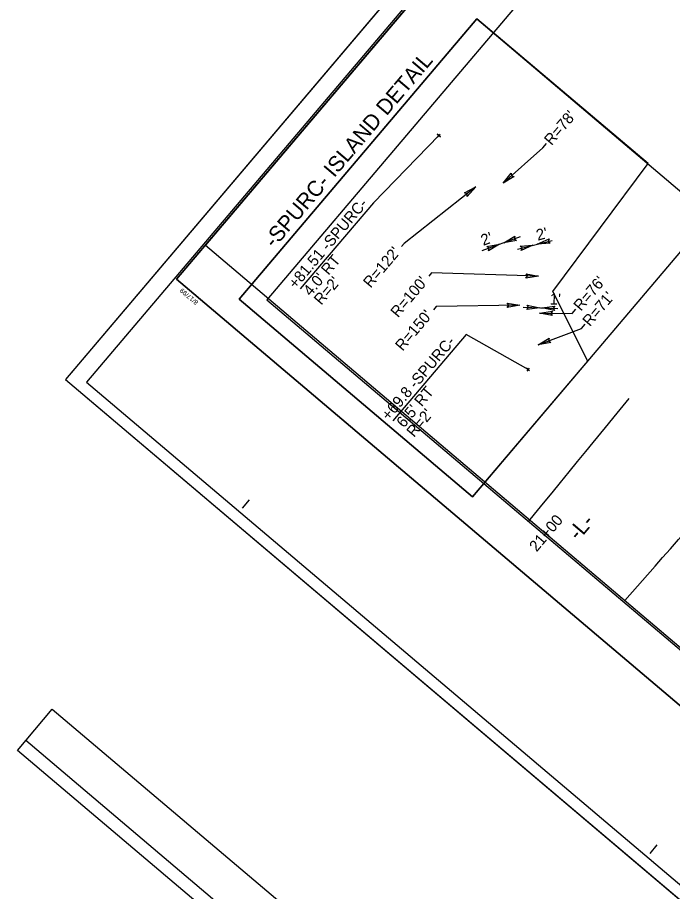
# Model space of a CAD drawing. Extents: x 1761753 to 1762923, y 422186 to 423380.
# Drawn here: x 1761753.2 to 1762047.4, y 422600.2 to 422992.9 of the extents above; entities that cross this region are included whole.
import ezdxf

# ---------------------------------------------------------------- set-up
doc = ezdxf.new("R2010")
doc.units = 0
for name, color, linetype in [('Default', 7, 'Continuous'), ('Prop Conc 2ft 6in Curb and Gutter', 7, 'Continuous'), ('Prop Conc 5in Monolithic Keyed In Island', 7, 'Continuous'), ('Prop Dimension Text', 7, 'Continuous'), ('Prop Grid Mask', 7, 'Continuous'), ('Prop Horizontal Alignment Station Label', 7, 'Continuous'), ('Prop RDY Traffic Signal CELL', 7, 'Continuous'), ('Prop Shade Heavy', 7, 'Continuous'), ('Sheet Cutting Line CELL', 7, 'Continuous'), ('Sheet Data Field CELL', 7, 'Continuous'), ('Sheet North Arrow CELL', 7, 'Continuous'), ('Sheet Plan CELL', 7, 'Continuous'), ('Sheet Plot Border Outside CELL', 7, 'Continuous'), ('Sheet Symbology CELL', 7, 'Continuous')]:
    doc.layers.add(name, color=color, linetype=linetype)

# ---------------------------------------------------------------- blocks, each defined once
blk = doc.blocks.new('Terminator')
at = {"layer": 'Sheet Data Field CELL'}
blk.add_lwpolyline([(-9, 1.55), (0, 0), (-9.05, -1.6), (-7.9, 0)], close=True, dxfattribs=at)

msp = doc.modelspace()

# ---------------------------------------------------------------- linework, layer by layer
at = {"layer": 'Default'}
for p, q in [((1761942.31, 422939.98), (1761941.73, 422940.47)), ((1761943.14, 422939.28), (1761942.31, 422939.98)), ((1761982.36, 422834.9), (1761981.78, 422835.39)), ((1761983.19, 422834.2), (1761982.36, 422834.9))]:
    msp.add_line(p, q, dxfattribs=at)
at = {"layer": 'Prop Conc 2ft 6in Curb and Gutter'}
msp.add_lwpolyline([(1762106.21, 422556.31), (1762536.95, 423064.78), (1762214.97, 423337.56), (1761784.22, 422829.09)], close=True, dxfattribs=at)
at = {"layer": 'Prop Conc 5in Monolithic Keyed In Island'}
msp.add_lwpolyline([(1761852.77, 422866.3), (1761959.54, 422992.34), (1762064.33, 422903.57), (1761957.56, 422777.53)], close=True, dxfattribs=at)
at = {"layer": 'Prop Dimension Text'}
for p, q in [((1762210.03, 423344.1), (1761774.75, 422830.29)), ((1761774.75, 422830.29), (1762108.95, 422547.17))]:
    msp.add_line(p, q, dxfattribs=at)
at = {"layer": 'Prop Grid Mask'}
for p, q in [((1761824.66, 422875.29), (1761824.66, 422875.29)), ((1761854.18, 422772.43), (1761857.41, 422776.26)), ((1762037.31, 422617.31), (1762040.54, 422621.12))]:
    msp.add_line(p, q, dxfattribs=at)
for points in [[(1762212.5, 423333.11), (1761824.66, 422875.29), (1762145.13, 422603.81), (1762532.96, 423061.62)], [(1762145.13, 422603.81), (1761824.66, 422875.28), (1762160.77, 423272.05), (1762206.57, 423233.25), (1762258.3, 423294.3), (1762532.96, 423061.62)]]:
    msp.add_lwpolyline(points, close=True, dxfattribs=at)
at = {"layer": 'Prop Horizontal Alignment Station Label'}
for points in [[(1762146.91, 422627.42), (1762512.32, 423058.75), (1762267, 423266.56), (1762215.18, 423205.39), (1762178.84, 423236.18), (1761865.25, 422866.02)], [(1761957.56, 422777.53), (1762009.27, 422838.57), (1761993.69, 422869.84), (1762036.36, 422927.27), (1761959.54, 422992.34), (1761852.77, 422866.3)]]:
    msp.add_lwpolyline(points, close=True, dxfattribs=at)
at = {"layer": 'Prop RDY Traffic Signal CELL'}
msp.add_lwpolyline([(1761824.66, 422875.28), (1762145.13, 422603.81), (1762532.96, 423061.61), (1762277.04, 423278.41), (1762215.18, 423205.39), (1762150.64, 423260.08)], close=True, dxfattribs=at)
at = {"layer": 'Prop Shade Heavy'}
msp.add_line((1761998.27, 422463.63), (1761756.96, 422668.05), dxfattribs=at)
msp.add_lwpolyline([(1761994.52, 422459.19), (1761753.21, 422663.61), (1761768.85, 422682.09), (1762010.16, 422477.67)], close=True, dxfattribs=at)
at = {"layer": 'Sheet Cutting Line CELL'}
for points in [[(1762027.69, 422821.77), (1762022.3, 422815.19), (1762017.07, 422808.73), (1762011.57, 422801.92), (1762008.28, 422797.88), (1762004.62, 422793.41), (1762000.78, 422788.74), (1761996.95, 422784.06), (1761993.11, 422779.39), (1761989.28, 422774.71), (1761985.2, 422769.73), (1761982.64, 422766.58)], [(1762026.02, 422730.92), (1762039.5, 422746.35), (1762042.91, 422750.24), (1762046.43, 422754.25), (1762050.07, 422758.38), (1762053.68, 422762.47), (1762057.14, 422766.4), (1762063.59, 422773.73), (1762070.08, 422781.07), (1762072.51, 422783.8)]]:
    msp.add_lwpolyline(points, dxfattribs=at)
at = {"layer": 'Sheet Data Field CELL'}
for points in [[(1761977.25, 422892.73), (1761971.59, 422891.72), (1761976.61, 422894.61), (1761976.27, 422893.42)], [(1761978.96, 422890.14), (1761984.69, 422890.59), (1761979.42, 422888.21), (1761979.87, 422889.36)], [(1761981.57, 422877.8), (1761987.2, 422876.65), (1761981.47, 422875.82), (1761982.23, 422876.81)], [(1761982.09, 422863.67), (1761987.72, 422862.5), (1761981.99, 422861.69), (1761982.75, 422862.67)]]:
    msp.add_lwpolyline(points, close=True, dxfattribs=at)
at = {"layer": 'Sheet North Arrow CELL'}
msp.add_lwpolyline([(1762108.95, 422547.17), (1762544.23, 423060.98), (1762210.03, 423344.1), (1761774.75, 422830.29)], close=True, dxfattribs=at)
at = {"layer": 'Sheet Plan CELL'}
for p, q in [((1761941.73, 422940.47), (1761943.14, 422939.28)), ((1761942.98, 422940.51), (1761941.83, 422939.16)), ((1761978.96, 422894.39), (1761961.75, 422888.14)), ((1761977.72, 422888.82), (1761993.34, 422892.79)), ((1761980.23, 422862.76), (1761995.89, 422862.22)), ((1761981.78, 422835.39), (1761983.19, 422834.2)), ((1761983.03, 422835.43), (1761981.88, 422834.08))]:
    msp.add_line(p, q, dxfattribs=at)
for points in [[(1761942.44, 422939.87), (1761913.05, 422909.71), (1761880.2, 422870.94)], [(1761971.31, 422918.41), (1761989.07, 422934.33), (1761990.73, 422936.3)], [(1761959.03, 422916.84), (1761926.86, 422891.43), (1761925.62, 422889.97)], [(1761987.2, 422876.65), (1761939.16, 422878.13), (1761937.92, 422876.67)], [(1761978.79, 422863.72), (1761941.25, 422863.09), (1761940.02, 422861.63)], [(1761987.68, 422860.12), (1762002.26, 422859.9), (1762003.92, 422861.88)], [(1761987.04, 422845.83), (1762006.51, 422853.13), (1762008.17, 422855.1)], [(1761982.49, 422834.79), (1761954.69, 422850.44), (1761921.84, 422811.66)]]:
    msp.add_lwpolyline(points, dxfattribs=at)
at = {"layer": 'Sheet Symbology CELL'}
msp.add_lwpolyline([(1762158.05, 422619.07), (1762520.03, 423046.36), (1762264.12, 423263.16), (1762215.18, 423205.39), (1762150.64, 423260.08), (1761837.59, 422890.55)], close=True, dxfattribs=at)

# ---------------------------------------------------------------- block references
at = {"layer": 'Sheet Data Field CELL'}
for p, xscale, yscale, rotation in [((1761971.31, 422918.41), 0.6300000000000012, 0.6299999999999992, -138.12107037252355), ((1761959.03, 422916.84), 0.6300000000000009, 0.6299999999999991, 38.2983472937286), ((1761986.63, 422891.08), 0.6300000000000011, 0.6299999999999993, -165.72248775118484), ((1761969.71, 422891.03), 0.6300000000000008, 0.6299999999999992, 19.95293068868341), ((1761978.79, 422863.72), 0.6300000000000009, 0.6299999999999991, 0.9662904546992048), ((1761987.68, 422860.12), 0.6300000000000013, 0.6299999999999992, 178.03768734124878), ((1761988.72, 422862.47), 0.6300000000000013, 0.6299999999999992, 178.03768734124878), ((1761987.04, 422845.83), 0.6300000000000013, 0.6299999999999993, -159.43386498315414)]:
    msp.add_blockref('Terminator', p, dxfattribs=dict(at, xscale=xscale, yscale=yscale, rotation=rotation))

# ---------------------------------------------------------------- texts
at = {"layer": 'Prop Dimension Text'}
for s, height, rotation, p in [('-SPURC- ISLAND DETAIL', 7, 49.7301, (1761868.52, 422888.92)), ("R=78'", 5, 49.7301, (1761993.04, 422935.13)), ('+81.51 -SPURC-', 5, 49.7301, (1761878.2, 422870.64)), ("2'", 5, 19.9529, (1761962.35, 422890.29)), ("2'", 5, 14.2775, (1761986.85, 422892.63)), ("R=122'", 5, 49.7301, (1761911.77, 422871.08)), ("4.0' RT", 5, 49.7301, (1761884.84, 422867.37)), ("R=2'", 5, 49.7301, (1761889.63, 422863.39)), ("R=100'", 5, 49.7301, (1761924.07, 422857.78)), ("R=76'", 5, 49.7301, (1762006.23, 422860.7)), ("1'", 5, 358.0377, (1761992.16, 422863.99)), ("R=71'", 5, 49.7301, (1762010.26, 422853.77)), ("R=150'", 5, 49.7301, (1761926.16, 422842.74)), ('+69.8 -SPURC-', 5, 49.7301, (1761919.95, 422811.5)), ("6.5' RT", 5, 49.7301, (1761926.71, 422808.25)), ("R=2'", 5, 49.7301, (1761931.25, 422803.99))]:
    msp.add_text(s, height=height, rotation=rotation, dxfattribs=at).set_placement(p)
at = {"layer": 'Prop Grid Mask'}
msp.add_text('8/17/99', height=2.1, rotation=139.7301, dxfattribs=at).set_placement((1761834.58, 422865.2))
at = {"layer": 'Sheet Plot Border Outside CELL'}
for s, height, p in [('21+00', 5, (1761986.35, 422752.55)), ('-L-', 7, (1762005.11, 422757.52))]:
    msp.add_text(s, height=height, rotation=49.7301, dxfattribs=at).set_placement(p)

doc.saveas('drawing.dxf')
